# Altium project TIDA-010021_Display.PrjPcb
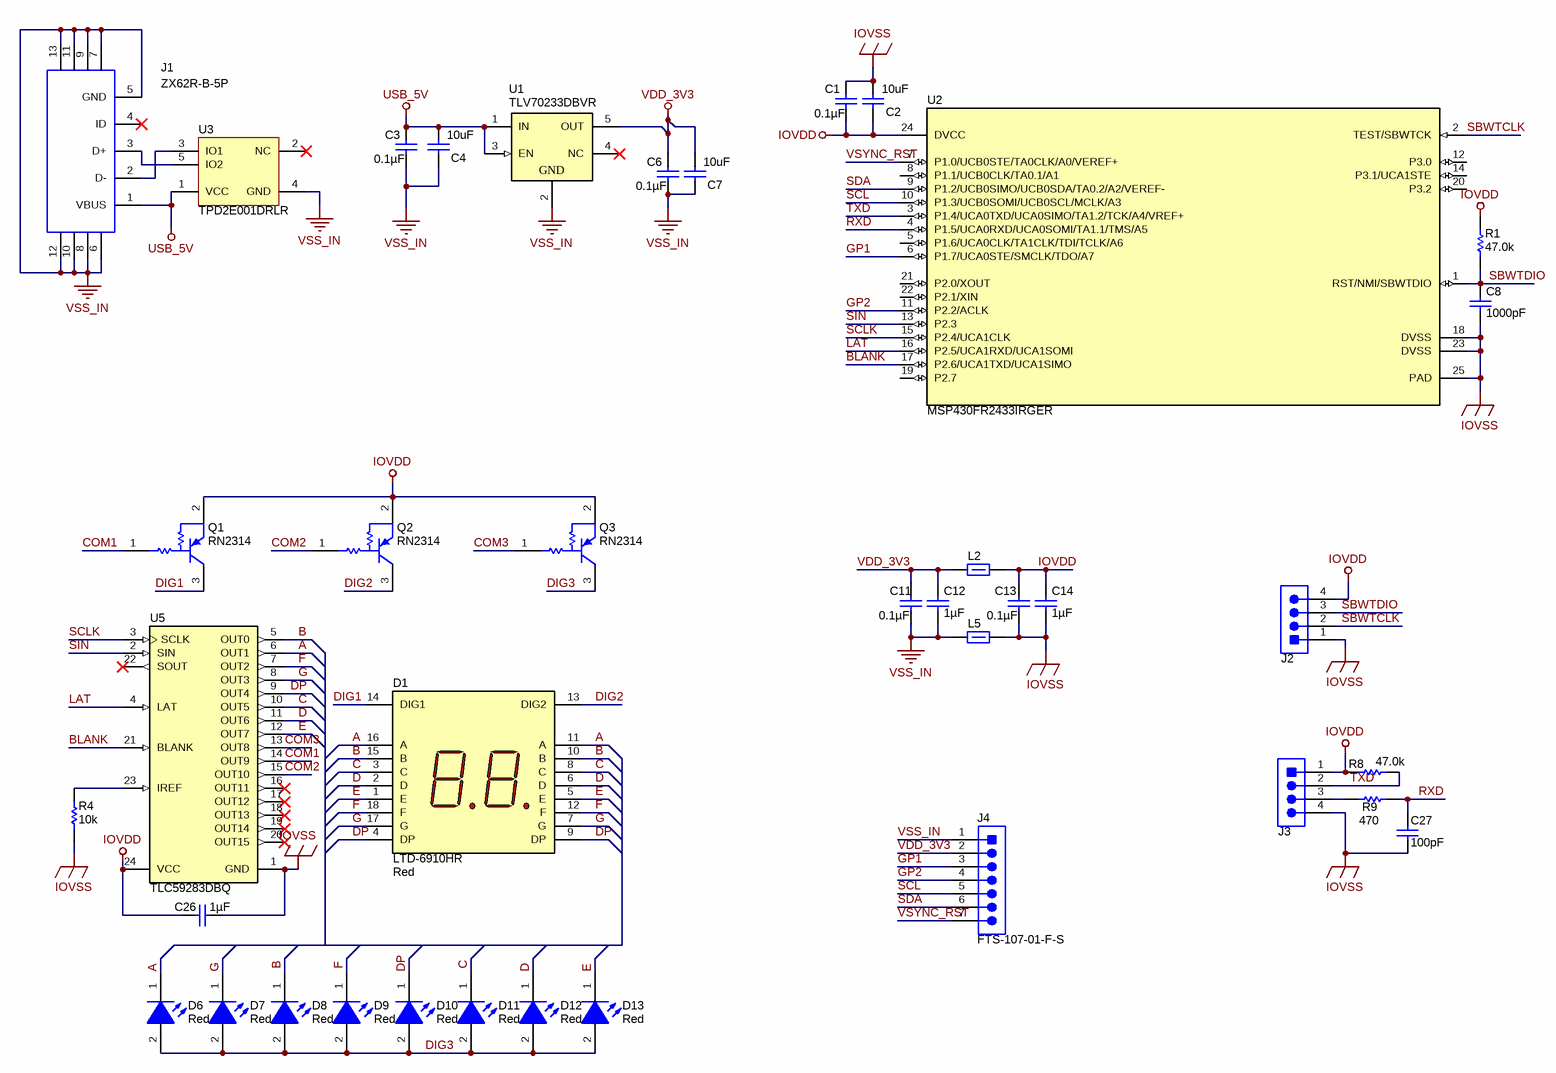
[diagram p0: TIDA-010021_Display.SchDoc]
EVM_Oderable: N/A; TID: 010021; TechSupport: http://www.ti.com/support; SCH_Rev: E1; PRJ_Title: Proximity Sensing Display Board; PRJ_Number: TIDA-010021; PRJ_Engineer: Richard Wang; PRJ_Customer: Public Release; PCB_Rev: E1; PCB_Layout: Richard Wang; CopyrightYear: 2018
3 sheets, 47 parts. Net scope: global (net labels, ports and power ports of the same name join across sheets).
Board file: TIDA-010021_Display.PcbDoc
Sheets:
  TIDA-010021_Display.SchDoc
  TIDA-010021_Display_CoverSheet.SchDoc
  TIDA-010021_Display_Hardware.SchDoc

## Sheet TIDA-010021_Display.SchDoc
size 431 x 279 mm; Date: Not shown in title block; ApprovedBy: Not shown in title block; CheckedBy: Not shown in title block; Author: Not shown in title block; CompanyName: Not shown in title block; DrawnBy: Richard Wang; Engineer: Not shown in title block; Organization: Not shown in title block; Address1: Not shown in title block; Address2: Not shown in title block; Address3: Not shown in title block; Address4: Not shown in title block; DocumentNumber: 1; Revision: Use project parameter SCH_Rev; SheetNumber: 2; SheetTotal: 3; PageSetup: Record=PageOptions¦CenterHorizontal=True¦CenterVertical=True¦PrintScale=1.00¦XCorrection=1.00¦YCorrection=1.00¦PrintKind=0¦BorderSize=5000000¦LeftOffset=0¦BottomOffset=0¦Orientation=2¦PaperLength=1000¦PaperWidth=1000¦Scale=100¦PaperSource=15¦PrintQuality=600¦MediaType=1¦DitherType=10¦PaperKind=Letter¦PrintScaleMode=1

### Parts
C1  ValueDisplayed: 0.1µF  [0402]  (hidden comment: 885012205037)
C2  value 10uF  [0402]  (hidden comment: CL05A106MP5NUNC)
C3  ValueDisplayed: 0.1µF  [0402]  (hidden comment: 885012205037)
C4  value 10uF  [0402]  (hidden comment: CL05A106MP5NUNC)
C6  ValueDisplayed: 0.1µF  [0402]  (hidden comment: 885012205037)
C7  value 10uF  [0402]  (hidden comment: CL05A106MP5NUNC)
C8  ValueDisplayed: 1000pF  [0402]  (hidden comment: 885012205044)
C11  ValueDisplayed: 0.1µF  [0402]  (hidden comment: 885012205037)
C12  ValueDisplayed: 1µF  [0402]  (hidden comment: GRM155R61A105KE15D)
C13  ValueDisplayed: 0.1µF  [0402]  (hidden comment: 885012205037)
C14  ValueDisplayed: 1µF  [0402]  (hidden comment: GRM155R61A105KE15D)
C26  ValueDisplayed: 1µF  [0402]  (hidden comment: GRM155R61A105KE15D)
C27  ValueDisplayed: 100pF  [0402]  (hidden comment: 885012205055)
D1  LTD-6910HR  value Red  [LTD-6910H_Red]
D6  value Red  [WL-SMCW_RED]  (hidden comment: 150060RS75000)
D7  value Red  [WL-SMCW_RED]  (hidden comment: 150060RS75000)
D8  value Red  [WL-SMCW_RED]  (hidden comment: 150060RS75000)
D9  value Red  [WL-SMCW_RED]  (hidden comment: 150060RS75000)
D10  value Red  [WL-SMCW_RED]  (hidden comment: 150060RS75000)
D11  value Red  [WL-SMCW_RED]  (hidden comment: 150060RS75000)
D12  value Red  [WL-SMCW_RED]  (hidden comment: 150060RS75000)
D13  value Red  [WL-SMCW_RED]  (hidden comment: 150060RS75000)
J1  ZX62R-B-5P  [Hirose_ZX62R-B-5P]
J2  GRPB041VWVN-RC  [Sullins_GRPB041VWVN-RC]  (value not drawn)
J3  GRPB041VWVN-RC  [Sullins_GRPB041VWVN-RC]  (value not drawn)
J4  FTS-107-01-F-S  [Samtec_FTS-107-01-x-S]
L2  MMZ1005S182ET000  [MMZ1005-E]  (value not drawn)
L5  MMZ1005S182ET000  [MMZ1005-E]  (value not drawn)
Q1  RN2314  [SOT-323]
Q2  RN2314  [SOT-323]
Q3  RN2314  [SOT-323]
R1  ValueDisplayed: 47.0k  [0402]  (hidden comment: RC0402FR-0747KL)
R4  ValueDisplayed: 10k  [0402]  (hidden comment: CRCW040210K0JNED)
R8  ValueDisplayed: 47.0k  [0402]  (hidden comment: RC0402FR-0747KL)
R9  ValueDisplayed: 470  [0402]  (hidden comment: RC0402FR-07470RL)
U1  TLV70233DBVR  [DBV0005A_N]
U2  MSP430FR2433IRGER  [RGE0024H]
U3  TPD2E001DRLR  [DRL0005A]
U5  TLC59283DBQ  [DBQ0024A_N]

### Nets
IOVDD: C1.2 C2.2 C13.1 C14.1 C26.1 J2.4 J3.1 L2.2 Q1.2(E) Q2.2(E) Q3.2(E) R1.2 R8.1 U2.24(DVCC) U5.24(VCC)
IOVSS: C1.1 C2.1 C8.2 C13.2 C14.2 C26.2 C27.2 J2.1 J3.4 L5.2 R4.1 U2.18(DVSS) U2.23(DVSS) U2.25(PAD) U5.1(GND)
USB_5V: C3.1 C4.1 J1.1(VBUS) U1.1(IN) U1.3(EN) U3.1(VCC)
VDD_3V3: C6.1 C7.1 C11.1 C12.1 J4.2 L2.1 U1.5(OUT)
VSS_IN: C3.2 C4.2 C6.2 C7.2 C11.2 C12.2 J1.5(GND) J1.6 J1.7 J1.8 J1.9 J1.10 J1.11 J1.12 J1.13 J4.1 L5.1 U1.2(GND) U3.4(GND)
A: D1.11(A) D1.16(A) D6.1(K) U5.6(OUT1)
B: D1.10(B) D1.15(B) D8.1(K) U5.5(OUT0)
BLANK: U2.17(P2.6/UCA1TXD/UCA1SIMO) U5.21(BLANK)
C: D1.3(C) D1.8(C) D11.1(K) U5.10(OUT5)
COM1: Q1.1(B) U5.14(OUT9)
COM2: Q2.1(B) U5.15(OUT10)
COM3: Q3.1(B) U5.13(OUT8)
D: D1.2(D) D1.6(D) D12.1(K) U5.11(OUT6)
DIG1: D1.14(DIG1) Q1.3(C)
DIG2: D1.13(DIG2) Q2.3(C)
DIG3: D6.2(A) D7.2(A) D8.2(A) D9.2(A) D10.2(A) D11.2(A) D12.2(A) D13.2(A) Q3.3(C)
DP: D1.4(DP) D1.9(DP) D10.1(K) U5.9(OUT4)
E: D1.1(E) D1.5(E) D13.1(K) U5.12(OUT7)
F: D1.12(F) D1.18(F) D9.1(K) U5.7(OUT2)
G: D1.7(G) D1.17(G) D7.1(K) U5.8(OUT3)
GP1: J4.3 U2.6(P1.7/UCA0STE/SMCLK/TDO/A7)
GP2: J4.4 U2.11(P2.2/ACLK)
LAT: U2.16(P2.5/UCA1RXD/UCA1SOMI) U5.4(LAT)
RXD: C27.1 R9.2 U2.4(P1.5/UCA0RXD/UCA0SOMI/TA1.1/TMS/A5)
SBWTCLK: J2.2 U2.2(TEST/SBWTCK)
SBWTDIO: C8.1 J2.3 R1.1 U2.1(RST/NMI/SBWTDIO)
SCL: J4.5 U2.10(P1.3/UCB0SOMI/UCB0SCL/MCLK/A3)
SCLK: U2.15(P2.4/UCA1CLK) U5.3(SCLK)
SDA: J4.6 U2.9(P1.2/UCB0SIMO/UCB0SDA/TA0.2/A2/VEREF-)
SIN: U2.13(P2.3) U5.2(SIN)
TXD: J3.2 R8.2 U2.3(P1.4/UCA0TXD/UCA0SIMO/TA1.2/TCK/A4/VREF+)
VSYNC_RST: J4.7 U2.7(P1.0/UCB0STE/TA0CLK/A0/VEREF+)
NetJ1_2: J1.2(D-) U3.3(IO1)
NetJ1_3: J1.3(D+) U3.5(IO2)
NetJ3_3: J3.3 R9.1
NetR4_2: R4.2 U5.23(IREF)

Not connected (* = marked no-connect by the designer): J1 4(ID)*; U1 4(NC)*; U2 5(P1.6/UCA0CLK/TA1CLK/TDI/TCLK/A6) 8(P1.1/UCB0CLK/TA0.1/A1) 12(P3.0) 14(P3.1/UCA1STE) 19(P2.7) 20(P3.2) 21(P2.0/XOUT) 22(P2.1/XIN); U3 2(NC)*; U5 16(OUT11)* 17(OUT12)* 18(OUT13)* 19(OUT14)* 20(OUT15)* 22(SOUT)*

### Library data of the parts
C1 C3 C6 C11 C13 = 885012205037: CAP, CERM, 0.1 µF, 16 V, +/- 10%, X7R, 0402; Manufacturer: Wurth Elektronik; Polarized: N; CompType: Capacitor; Value: 0.1uF; U/M: EA; Cap_F: 0.0000001; Tolerance_%: 10; Value1: Unknown; VDC_V: 16; Value2: 16V; TaMin_C: -55; TaMax_C: 125; SizeArea_mm2: 0.5; SizeAreaWB_mm2: 3; SizeX_mm: 1; SizeZ_mm: 0.6; AEC Category: Q200
C2 C4 C7 = CMP-0006339-1: CAP, CERM, 10 uF, 10 V, +/- 20%, X5R, 0402; Manufacturer: Samsung Electro-Mechanics; TaMin_C: -55°C; Polarized: N; SizeAreaWB_mm2: 3; Value1: Unknown; U/M: EA; TaMax_C: 85°C; SizeZ_mm: 0.6; SizeX_mm: 1; SizeY_mm: 0.5; Value2: 10V; CompType: Capacitor; Cap_F: 10µF; AEC Category: Q200
C8 = 885012205044: CAP, CERM, 1000 pF, 25 V, +/- 10%, X7R, 0402; Manufacturer: Wurth Elektronik; Polarized: N; CompType: Capacitor; Value: 1000pF; U/M: EA; Cap_F: 0.000000001; Tolerance_%: 10; Value1: Unknown; VDC_V: 25; Value2: 25V; TaMin_C: -55; TaMax_C: 125; SizeArea_mm2: 0.5; SizeAreaWB_mm2: 3; SizeX_mm: 1; SizeZ_mm: 0.6; AEC Category: Q200
C12 C14 C26 = GRM155R61A105KE15D: CAP, CERM, 1 µF, 10 V, +/- 10%, X5R, 0402; Manufacturer: MuRata; Polarized: N; CompType: Capacitor; Value: 1uF; U/M: EA; Cap_F: 0.000001; Tolerance_%: 10; Value1: Unknown; Value2: 10V; TaMin_C: -55; TaMax_C: 85; SizeArea_mm2: 0.5; SizeAreaWB_mm2: 3; SizeX_mm: 1; SizeZ_mm: 0.6; AEC Category: Q200
C27 = 885012205055: CAP, CERM, 100 pF, 50 V, +/- 10%, X7R, 0402; Manufacturer: Wurth Elektronik; Polarized: N; CompType: Capacitor; Value: 100pF; U/M: EA; Cap_F: 0.0000000001; Tolerance_%: 10; Value1: Unknown; VDC_V: 50; Value2: 50V; TaMin_C: -55; TaMax_C: 125; SizeArea_mm2: 0.5; SizeAreaWB_mm2: 3; SizeX_mm: 1; SizeZ_mm: 0.6; AEC Category: Q200
D1 = LTD-6910HR: LED, Red, TH; Manufacturer: Lite-On; SymbolCreator: Altium; Type: GaAsP on GaP; Vf_V: 2; Value2: 2V; Io_A: 0.02; Vr_V: 5; Ir_A: 0.0001; Tjmax_C: 85; Power_TotalModule: 0.075; Value1: 0.075W; SizeAreaWB_mm2: 568.35; SizeArea_mm2: 476.25; SizeX_mm: 19.05; SizeY_mm: 25; SizeZ_mm: 8.25; U/M: EA
D6-D13 = 150060RS75000: LED, Red, SMD; Manufacturer: Wurth Elektronik; Type: AlInGaP; Vf_V: 2; Value2: 2V; Io_A: 0.03; Vr_V: 5; Tjmax_C: 85; Power_TotalModule: 0.072; Value1: 0.072W; Angle: 140; U/M: EA
J1 = ZX62R-B-5P: Connector, Receptacle, Micro-USB Type B, SMT; Manufacturer: Hirose Electric Co. Ltd.; SymbolCreator: a0799628; U/M: EA
J2 J3 = GRPB041VWVN-RC: Header, 50mil, 4x1, Gold, TH; Manufacturer: Sullins Connector Solutions; SymbolCreator: a0412235
J4 = CMP-0075532-1: Header, 1.27mm, 7x1, Gold, TH; Manufacturer: Samtec; Pitch_mm: 1.27; Gender: Male; CT: False; Shrouded: N; Row_Count: 1; CNHeader: True
L2 L5 = CMP-0080017-1: Inductor, Ferrite Bead, Ferrite, 0.2 A, 2.1 ohm, SMD; Manufacturer: TDK; SizeAreaWB_mm2: 3; SizeArea_mm2: 0.5; AEC Qualified: N; AEC Category: Q200; SizeZ_mm: 0.55; Imax_A: 2dA; Value2: 0.2A; Value1: 2.1 ohm; DCR_ohm: 2.1; SizeX_mm: 1
Q1-Q3 = PDTA124EU,115, NXP Semiconductor: Transistor, PNP, 50 V, 0.1 A, SOT-323; Manufacturer: Toshiba; SymbolCreator: a0411947; PNP: 1; NPN: 0; Vceo_V: 50; Vcesat1_V: 0.15; Value: 50 V; IcRated_A: 0.1; Value1: 0.1 A; TaMin_C: -65; TaMax_C: 150; SizeAreaWB_mm2: 10.24; SizeArea_mm2: 4.84; SizeX_mm: 2.2; SizeZ_mm: 1.1; CompType: BJT; U/M: EA; AEC Category: Q101
R1 R8 = RC0402FR-0747KL: RES, 47.0 k, 1%, 0.0625 W, 0402; Manufacturer: Yageo America; CompType: Resistor; Value: 47.0k; Res_ohm: 47000; Value_Code: 47k0; Tolerance_%: 1; Power_W: 0.0625; VDC_V: 50; TempCo: 100 ppm/C; SizeArea_mm2: 0.5; SizeZ_mm: 0.6; U/M: EA; AEC Category: Q200; AEC Qualified: N
R4 = CRCW040210K0JNED: RES, 10 k, 5%, 0.063 W, 0402; Manufacturer: Vishay-Dale; CompType: Resistor; Value: 10k; Res_ohm: 10000; Value_Code: 10k0; Tolerance_%: 5; Power_W: 0.063; Value2: 0.063W; VDC_V: 50; TempCo: 200 ppm/C; SizeArea_mm2: 0.5; SizeX_mm: 1; SizeZ_mm: 0.6; EIA_Code: E24; U/M: EA; AEC Category: Q200
R9 = RC0402FR-07470RL: RES, 470, 1%, 0.063 W, 0402; Manufacturer: Yageo America; CompType: Resistor; Value: 470; Value_Code: 470R; Tolerance_%: 1; Power_W: 0.063; Value2: 0.063W; VDC_V: 50; TempCo: 100 ppm/C; SizeArea_mm2: 0.5; SizeZ_mm: 0.6; U/M: EA; AEC Category: Q200; AEC Qualified: N
U1 = TLV70233DBVR: Single Output LDO, 300 mA, Fixed 3.3 V Output, 2 to 5.5 V Input, with Low IQ, 5-pin SOT-23 (DBV), -40 to 125 degC, Green (RoHS & no Sb/Br); Manufacturer: Texas Instruments; Alternate PartNumber: Equivalent; Accuracy(%): 2; Fixed Output Options(V): 3.3; Iout(Max)(A): 0.3; Iq(Typ)(mA): 0.03; SubFamily: Single Channel LDO; Vdo(Typ)(mV): 220; Vin(Max)(V): 5.5
U2 = MSP430FR2433IRGER: MSP430FR2433 16 MHz Ultra-Low-Power Microcontroller with 16 KB FRAM, 4 KB RAM, 19 IO, 4 Timers, RGE0024H (VQFN-24); Alternate PartNumber: MSP430FR2433IRGET; Manufacturer: Texas Instruments; SymbolCreator: Altium; SizeArea_mm2: 16; SizeAreaWB_mm2: 25; SizeX_mm: 4; SizeZ_mm: 1; CompType: IC; U/M: EA
U3 = TPD2E001DRLR: Low-Capacitance + / - 15 kV ESD-Protection Array for High-Speed Data Interfaces, 2 Channels, -40 to +85 degC, 5-pin SOT (DRL), Green (RoHS & no Sb/Br); Manufacturer: Texas Instruments; Alternate Manufacturer: None; Alternate PartNumber: Equivalent; Breakdown Voltage(Min)(V): 11; IEC 61000-4-2 Air-Gap(+/- kV): 15; IEC 61000-4-2 Contact(+/- kV): 8; IO Capacitance(Typ)(pF): 1.5; IO Leakage Current(nA): 1; SubFamily: ESD Solution; USB High Speed: TRUE
U5 = TLC59282DBQ: 16-Channel Constant Current LED Driver with 4-Channel Grouped Delay, 3 to 5.5 V, -40 to 85 degC, 24-pin SOP (DBQ24), Green (RoHS & no Sb/Br); Manufacturer: Texas Instruments; Alternate PartNumber: Equivalent; Vin(Max)(V): 5.5; Vin(Min)(V): 3

## Sheet TIDA-010021_Display_CoverSheet.SchDoc
size 431 x 279 mm; Date: Not shown in title block; ApprovedBy: Not shown in title block; CheckedBy: Not shown in title block; Author: Not shown in title block; CompanyName: Not shown in title block; DrawnBy: Richard Wang; Engineer: Not shown in title block; Organization: Not shown in title block; Address1: Not shown in title block; Address2: Not shown in title block; Address3: Not shown in title block; Address4: Not shown in title block; DocumentNumber: 1; Revision: Use project parameter SCH_Rev; SheetNumber: 1; SheetTotal: 3; PageSetup: Record=PageOptions¦CenterHorizontal=True¦CenterVertical=True¦PrintScale=1.00¦XCorrection=1.00¦YCorrection=1.00¦PrintKind=0¦BorderSize=5000000¦LeftOffset=0¦BottomOffset=0¦Orientation=2¦PaperLength=1000¦PaperWidth=1000¦Scale=100¦PaperSource=15¦PrintQuality=600¦MediaType=1¦DitherType=10¦PaperKind=Letter¦PrintScaleMode=1
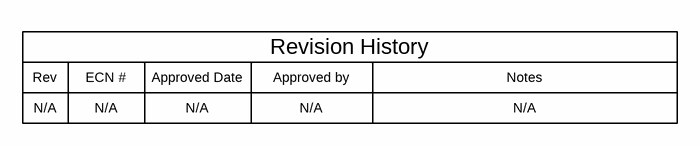
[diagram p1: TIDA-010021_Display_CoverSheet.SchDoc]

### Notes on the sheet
- Rev
- N/A
- ECN #
- Approved Date
- Approved by
- Revision History
- Notes

## Sheet TIDA-010021_Display_Hardware.SchDoc
size 431 x 279 mm; Date: Not shown in title block; ApprovedBy: Not shown in title block; CheckedBy: Not shown in title block; Author: Not shown in title block; CompanyName: Not shown in title block; DrawnBy: Richard Wang; Engineer: Richard Wang; Organization: Not shown in title block; Address1: Not shown in title block; Address2: Not shown in title block; Address3: Not shown in title block; Address4: Not shown in title block; DocumentNumber: 1; Revision: Use project parameter SCH_Rev; SheetNumber: 3; SheetTotal: 3; PageSetup: Record=PageOptions¦CenterHorizontal=True¦CenterVertical=True¦PrintScale=1.00¦XCorrection=1.00¦YCorrection=1.00¦PrintKind=0¦BorderSize=5000000¦LeftOffset=0¦BottomOffset=0¦Orientation=2¦PaperLength=1000¦PaperWidth=1000¦Scale=100¦PaperSource=15¦PrintQuality=600¦MediaType=1¦DitherType=10¦PaperKind=Letter¦PrintScaleMode=1
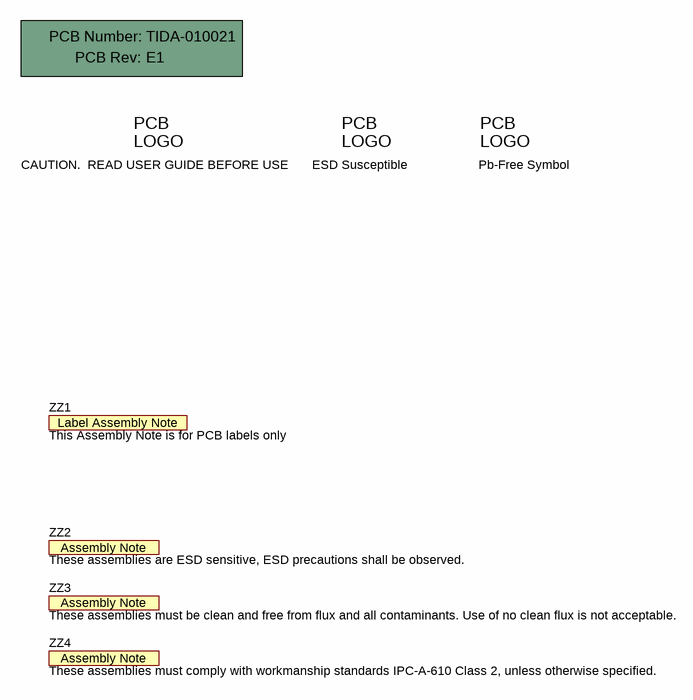
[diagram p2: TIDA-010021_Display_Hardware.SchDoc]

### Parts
!PCB  Printed Circuit Board  (value not drawn)  (mechanical)
Caution  CAUTION.  READ USER GUIDE BEFORE USE  [IEC_Caution_small]  (no BOM)
ESD  ESD Susceptible  [ESD_Overlay_small]  (no BOM)
Logo2  Pb-Free Symbol  [Pb-Free_Overlay_Small]  (no BOM)
ZZ1  This Assembly Note is for PCB labels only  [AssemblyNoteLabel]  (no BOM)
ZZ2  These assemblies are ESD sensitive, ESD precautions shall be observed.  [AssemblyNote]  (no BOM)
ZZ3  These assemblies must be clean and free from flux and all contaminants. Use of no clean flux is not acceptable.  [AssemblyNote]  (no BOM)
ZZ4  These assemblies must comply with workmanship standards IPC-A-610 Class 2, unless otherwise specified.  [AssemblyNote]  (no BOM)

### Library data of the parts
!PCB = PCB: Manufacturer: Any; PartNumber: TIDA-010021; SymbolCreator: a0412235
Caution = IEC_Caution: IEC 61010-1 Caution Warning; SymbolCreator: a0412235
ESD = ESD_Susceptible: ESD Susceptible Symbol; SymbolCreator: a0412235
Logo2 = Pb-Free: SymbolCreator: a0412235
ZZ1 = AssemblyNoteLabel: SymbolCreator: a0412235
ZZ2-ZZ4 = AssemblyNote: SymbolCreator: codlsc

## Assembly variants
001: not fitted FID1 FID2 FID3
